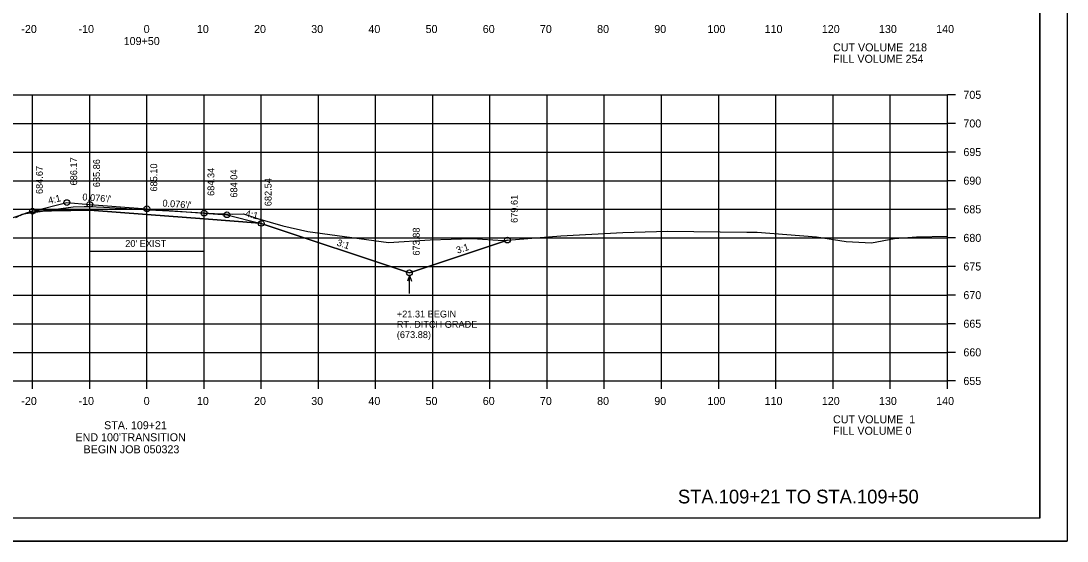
# Model space of a CAD drawing. Extents: x 1360146 to 1361431, y 631444 to 632352.
# Drawn here: x 1360296.7 to 1360479.7, y 631657.5 to 631748.4 of the extents above; entities that cross this region are included whole.
import ezdxf

# ---------------------------------------------------------------- set-up
doc = ezdxf.new("R2010")
doc.units = 0
for name, color, linetype in [('Default', 7, 'Continuous'), ('R_Alt Surface', 7, 'Continuous'), ('R_Axis', 7, 'Continuous'), ('R_Axis Annot', 7, 'Continuous'), ('R_Border', 7, 'Continuous'), ('R_Draft', 7, 'Continuous'), ('R_Exist Surface', 7, 'Continuous'), ('R_Fin Surface', 7, 'Continuous'), ('R_Grid', 7, 'Continuous'), ('R_No Plot', 7, 'Continuous'), ('R_Water Annot', 7, 'Continuous'), ('R_Xsect Elev', 7, 'Continuous'), ('R_Xsect Slope', 7, 'Continuous')]:
    doc.layers.add(name, color=color, linetype=linetype)

msp = doc.modelspace()

# ---------------------------------------------------------------- linework, layer by layer
at = {"layer": 'Default'}
for p, q in [((1360308.77, 631707.51), (1360308.77, 631708.88)), ((1360308.77, 631708.17), (1360328.77, 631708.17)), ((1360328.77, 631707.51), (1360328.77, 631708.88))]:
    msp.add_line(p, q, dxfattribs=at)
at = {"layer": 'R_Alt Surface'}
msp.add_lwpolyline([(1360298.75, 631715.14), (1360308.77, 631715.34), (1360318.77, 631714.58), (1360328.77, 631713.82), (1360338.55, 631713.07)], dxfattribs=at)
at = {"layer": 'R_Axis'}
for p, q in [((1360458.77, 631685.48), (1360458.77, 631735.48)), ((1360460.17, 631735.48), (1360458.77, 631735.48)), ((1360460.17, 631730.48), (1360458.77, 631730.48)), ((1360460.17, 631725.48), (1360458.77, 631725.48)), ((1360460.17, 631720.48), (1360458.77, 631720.48)), ((1360460.17, 631715.48), (1360458.77, 631715.48)), ((1360460.17, 631710.48), (1360458.77, 631710.48)), ((1360460.17, 631705.48), (1360458.77, 631705.48)), ((1360460.17, 631700.48), (1360458.77, 631700.48)), ((1360460.17, 631695.48), (1360458.77, 631695.48)), ((1360460.17, 631690.48), (1360458.77, 631690.48)), ((1360178.77, 631685.48), (1360458.77, 631685.48)), ((1360298.77, 631684.08), (1360298.77, 631685.48)), ((1360308.77, 631684.08), (1360308.77, 631685.48)), ((1360318.77, 631684.08), (1360318.77, 631685.48)), ((1360328.77, 631684.08), (1360328.77, 631685.48)), ((1360338.77, 631684.08), (1360338.77, 631685.48)), ((1360348.77, 631684.08), (1360348.77, 631685.48)), ((1360358.77, 631684.08), (1360358.77, 631685.48)), ((1360368.77, 631684.08), (1360368.77, 631685.48)), ((1360378.77, 631684.08), (1360378.77, 631685.48)), ((1360388.77, 631684.08), (1360388.77, 631685.48)), ((1360398.77, 631684.08), (1360398.77, 631685.48)), ((1360408.77, 631684.08), (1360408.77, 631685.48)), ((1360418.77, 631684.08), (1360418.77, 631685.48)), ((1360428.77, 631684.08), (1360428.77, 631685.48)), ((1360438.77, 631684.08), (1360438.77, 631685.48)), ((1360448.77, 631684.08), (1360448.77, 631685.48)), ((1360458.77, 631684.08), (1360458.77, 631685.48)), ((1360460.17, 631685.48), (1360458.77, 631685.48))]:
    msp.add_line(p, q, dxfattribs=at)
at = {"layer": 'R_Border'}
for q in [(1360474.95, 631866.94), (1360158.77, 631661.48)]:
    msp.add_line((1360474.95, 631661.48), q, dxfattribs=at)
at = {"layer": 'R_Exist Surface'}
msp.add_lwpolyline([(1360295.86, 631714.04), (1360296.98, 631714.63), (1360297.2, 631714.68), (1360305.86, 631715.93), (1360307.82, 631715.97), (1360308.59, 631715.98), (1360311.22, 631715.84), (1360319.14, 631715.41), (1360322.66, 631715.2), (1360330.57, 631714.72), (1360333.69, 631714.61), (1360335.67, 631714.71), (1360338.09, 631713.84), (1360342.54, 631712.61), (1360346.89, 631711.59), (1360361.02, 631709.65), (1360368.32, 631710.13), (1360375.63, 631710.36), (1360381.07, 631710.03), (1360391.17, 631710.85), (1360401.98, 631711.45), (1360407.92, 631711.61), (1360409.74, 631711.66), (1360423.68, 631711.5), (1360425.5, 631711.48), (1360435.86, 631710.65), (1360441.06, 631709.83), (1360445.52, 631709.63), (1360449.51, 631710.39), (1360453.39, 631710.67), (1360458.77, 631710.81)], dxfattribs=at)
at = {"layer": 'R_Fin Surface'}
msp.add_lwpolyline([(1360243.47, 631709.45), (1360262.57, 631703.08), (1360297.47, 631714.72), (1360297.48, 631714.72), (1360297.49, 631714.72), (1360297.49, 631714.72), (1360298.75, 631715.14), (1360298.77, 631715.15), (1360304.77, 631716.65), (1360308.77, 631716.34), (1360318.77, 631715.58), (1360328.77, 631714.82), (1360332.77, 631714.52), (1360338.55, 631713.07), (1360338.77, 631713.02), (1360364.68, 631704.38), (1360381.82, 631710.1)], dxfattribs=at)
at = {"layer": 'R_Grid'}
for p, q in [((1360178.77, 631735.48), (1360458.77, 631735.48)), ((1360298.77, 631685.48), (1360298.77, 631735.48)), ((1360308.77, 631685.48), (1360308.77, 631735.48)), ((1360318.77, 631685.48), (1360318.77, 631735.48)), ((1360328.77, 631685.48), (1360328.77, 631735.48)), ((1360338.77, 631685.48), (1360338.77, 631735.48)), ((1360348.77, 631685.48), (1360348.77, 631735.48)), ((1360358.77, 631685.48), (1360358.77, 631735.48)), ((1360368.77, 631685.48), (1360368.77, 631735.48)), ((1360378.77, 631685.48), (1360378.77, 631735.48)), ((1360388.77, 631685.48), (1360388.77, 631735.48)), ((1360398.77, 631685.48), (1360398.77, 631735.48)), ((1360408.77, 631685.48), (1360408.77, 631735.48)), ((1360418.77, 631685.48), (1360418.77, 631735.48)), ((1360428.77, 631685.48), (1360428.77, 631735.48)), ((1360438.77, 631685.48), (1360438.77, 631735.48)), ((1360448.77, 631685.48), (1360448.77, 631735.48)), ((1360458.77, 631685.48), (1360458.77, 631735.48)), ((1360178.77, 631730.48), (1360458.77, 631730.48)), ((1360178.77, 631725.48), (1360458.77, 631725.48)), ((1360178.77, 631720.48), (1360458.77, 631720.48)), ((1360178.77, 631715.48), (1360458.77, 631715.48)), ((1360178.77, 631710.48), (1360458.77, 631710.48)), ((1360178.77, 631705.48), (1360458.77, 631705.48)), ((1360178.77, 631700.48), (1360458.77, 631700.48)), ((1360178.77, 631695.48), (1360458.77, 631695.48)), ((1360178.77, 631690.48), (1360458.77, 631690.48)), ((1360178.77, 631685.48), (1360458.77, 631685.48))]:
    msp.add_line(p, q, dxfattribs=at)
at = {"layer": 'R_No Plot'}
msp.add_line((1360146.37, 631657.5), (1360479.7, 631657.5), dxfattribs=at)
for points in [[(1360146.36, 631870.84), (1360479.7, 631870.84), (1360479.7, 631657.5), (1360146.36, 631657.5)], [(1360392.69, 631866.94), (1360392.69, 631857.06), (1360428.42, 631857.06), (1360428.42, 631854.14), (1360451.62, 631854.14), (1360451.62, 631829.81), (1360474.95, 631829.81), (1360474.95, 631661.48), (1360158.77, 631661.48), (1360158.77, 631866.94)], [(1360297.49, 631714.72), (1360300.67, 631715.18), (1360298.75, 631715.14), (1360297.49, 631714.72)], [(1360300.67, 631715.18), (1360305.86, 631715.93), (1360307.82, 631715.97), (1360308.59, 631715.98), (1360311.22, 631715.84), (1360319.14, 631715.41), (1360322.66, 631715.2), (1360330.57, 631714.72), (1360333.69, 631714.61), (1360335.67, 631714.71), (1360338.09, 631713.84), (1360342.54, 631712.61), (1360346.89, 631711.59), (1360361.02, 631709.65), (1360368.32, 631710.13), (1360375.63, 631710.36), (1360381.07, 631710.03), (1360381.82, 631710.1), (1360364.68, 631704.38), (1360338.77, 631713.02), (1360338.55, 631713.07), (1360328.77, 631713.82), (1360318.77, 631714.58), (1360308.77, 631715.34)], [(1360296.58, 631714.42), (1360296.98, 631714.63), (1360297.2, 631714.68), (1360297.49, 631714.72), (1360297.48, 631714.72), (1360297.47, 631714.72)]]:
    msp.add_lwpolyline(points, close=True, dxfattribs=at)
for centre in [(1360304.77, 631716.65), (1360308.77, 631716.34), (1360298.77, 631715.15), (1360318.77, 631715.58), (1360328.77, 631714.82), (1360332.77, 631714.52), (1360338.77, 631713.02), (1360381.82, 631710.1), (1360364.68, 631704.38)]:
    msp.add_circle(centre, 0.5, dxfattribs=at)
at = {"layer": 'R_Water Annot'}
for p, q in [((1360364.68, 631703.88), (1360364.33, 631702.92)), ((1360364.68, 631700.74), (1360364.68, 631703.88)), ((1360364.68, 631703.88), (1360365.03, 631702.92))]:
    msp.add_line(p, q, dxfattribs=at)

# ---------------------------------------------------------------- texts
at = {"layer": 'Default'}
for s, p in [("20' EXIST", (1360314.98, 631708.9)), ('+21.31 BEGIN', (1360362.48, 631696.57)), ('RT. DITCH GRADE', (1360362.48, 631694.77)), ('(673.88)', (1360362.48, 631692.97))]:
    msp.add_text(s, height=1.2, dxfattribs=at).set_placement(p)
at = {"layer": 'R_Axis Annot'}
for s, p in [('-20', (1360296.81, 631746.28)), ('-10', (1360306.81, 631746.28)), ('0', (1360318.21, 631746.28)), ('10', (1360327.51, 631746.28)), ('20', (1360337.51, 631746.28)), ('30', (1360347.51, 631746.28)), ('40', (1360357.51, 631746.28)), ('50', (1360367.51, 631746.28)), ('60', (1360377.51, 631746.28)), ('70', (1360387.51, 631746.28)), ('80', (1360397.51, 631746.28)), ('90', (1360407.51, 631746.28)), ('100', (1360416.81, 631746.28)), ('110', (1360426.81, 631746.28)), ('120', (1360436.81, 631746.28)), ('130', (1360446.81, 631746.28)), ('140', (1360456.81, 631746.28)), ('109+50', (1360314.71, 631744.18)), ('CUT VOLUME  218', (1360438.77, 631743.08)), ('FILL VOLUME 254', (1360438.77, 631741.08)), ('705', (1360461.57, 631734.78)), ('700', (1360461.57, 631729.78)), ('695', (1360461.57, 631724.78)), ('690', (1360461.57, 631719.78)), ('685', (1360461.57, 631714.78)), ('680', (1360461.57, 631709.78)), ('675', (1360461.57, 631704.78)), ('670', (1360461.57, 631699.78)), ('665', (1360461.57, 631694.78)), ('660', (1360461.57, 631689.78)), ('655', (1360461.57, 631684.78)), ('-20', (1360296.81, 631681.28)), ('-10', (1360306.81, 631681.28)), ('0', (1360318.21, 631681.28)), ('10', (1360327.51, 631681.28)), ('20', (1360337.51, 631681.28)), ('30', (1360347.51, 631681.28)), ('40', (1360357.51, 631681.28)), ('50', (1360367.51, 631681.28)), ('60', (1360377.51, 631681.28)), ('70', (1360387.51, 631681.28)), ('80', (1360397.51, 631681.28)), ('90', (1360407.51, 631681.28)), ('100', (1360416.81, 631681.28)), ('110', (1360426.81, 631681.28)), ('120', (1360436.81, 631681.28)), ('130', (1360446.81, 631681.28)), ('140', (1360456.81, 631681.28)), ('STA. 109+21', (1360311.29, 631677.04)), ('CUT VOLUME  1', (1360438.77, 631678.08)), ('FILL VOLUME 0', (1360438.77, 631676.08)), ("END 100'TRANSITION", (1360306.28, 631674.94)), ('BEGIN JOB 050323', (1360307.69, 631672.84))]:
    msp.add_text(s, height=1.4, dxfattribs=at).set_placement(p)
at = {"layer": 'R_Draft'}
msp.add_text('STA.109+21 TO STA.109+50', height=2.4, dxfattribs=at).set_placement((1360411.65, 631664.08))
at = {"layer": 'R_Xsect Elev'}
for s, p in [('686.17', (1360306.57, 631719.65)), ('685.86', (1360310.57, 631719.34)), ('684.67', (1360300.57, 631718.15)), ('685.10', (1360320.57, 631718.58)), ('684.34', (1360330.57, 631717.82)), ('684.04', (1360334.57, 631717.52)), ('682.54', (1360340.57, 631716.02)), ('679.61', (1360383.62, 631713.1)), ('673.88', (1360366.48, 631707.38))]:
    msp.add_text(s, height=1.2, rotation=90, dxfattribs=at).set_placement(p)
at = {"layer": 'R_Xsect Slope'}
for s, rotation, p in [('4:1', 14.0362, (1360301.65, 631716.38)), ("0.076'/'", 355.6497, (1360307.45, 631717.05)), ("0.076'/'", 355.6497, (1360321.45, 631715.98)), ('4:1', 345.9638, (1360335.89, 631714.25)), ('3:1', 341.5651, (1360351.88, 631709.17)), ('3:1', 18.4349, (1360373.09, 631707.71))]:
    msp.add_text(s, height=1.2, rotation=rotation, dxfattribs=at).set_placement(p)

doc.saveas('drawing.dxf')
